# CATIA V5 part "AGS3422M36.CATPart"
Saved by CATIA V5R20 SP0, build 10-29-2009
Part number: AGS3422M36
Definition: NONE
Nomenclature: AGS3422M36
Source: Unknown
Description: AGS3422M36
Bounding box of the stored display mesh (mm): x -39 to 45, y -37 to 37, z -37 to 37
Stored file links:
  C:\Users\Utente\Desktop\IO LAVORO\3D X SITO CF\X SITO\PLASTICA\AGS\AGS3422M36.CATPart
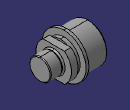
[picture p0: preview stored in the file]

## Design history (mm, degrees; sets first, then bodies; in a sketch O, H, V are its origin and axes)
Body1 "AGS3422M36" (main body)
  Solid1: solid without history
